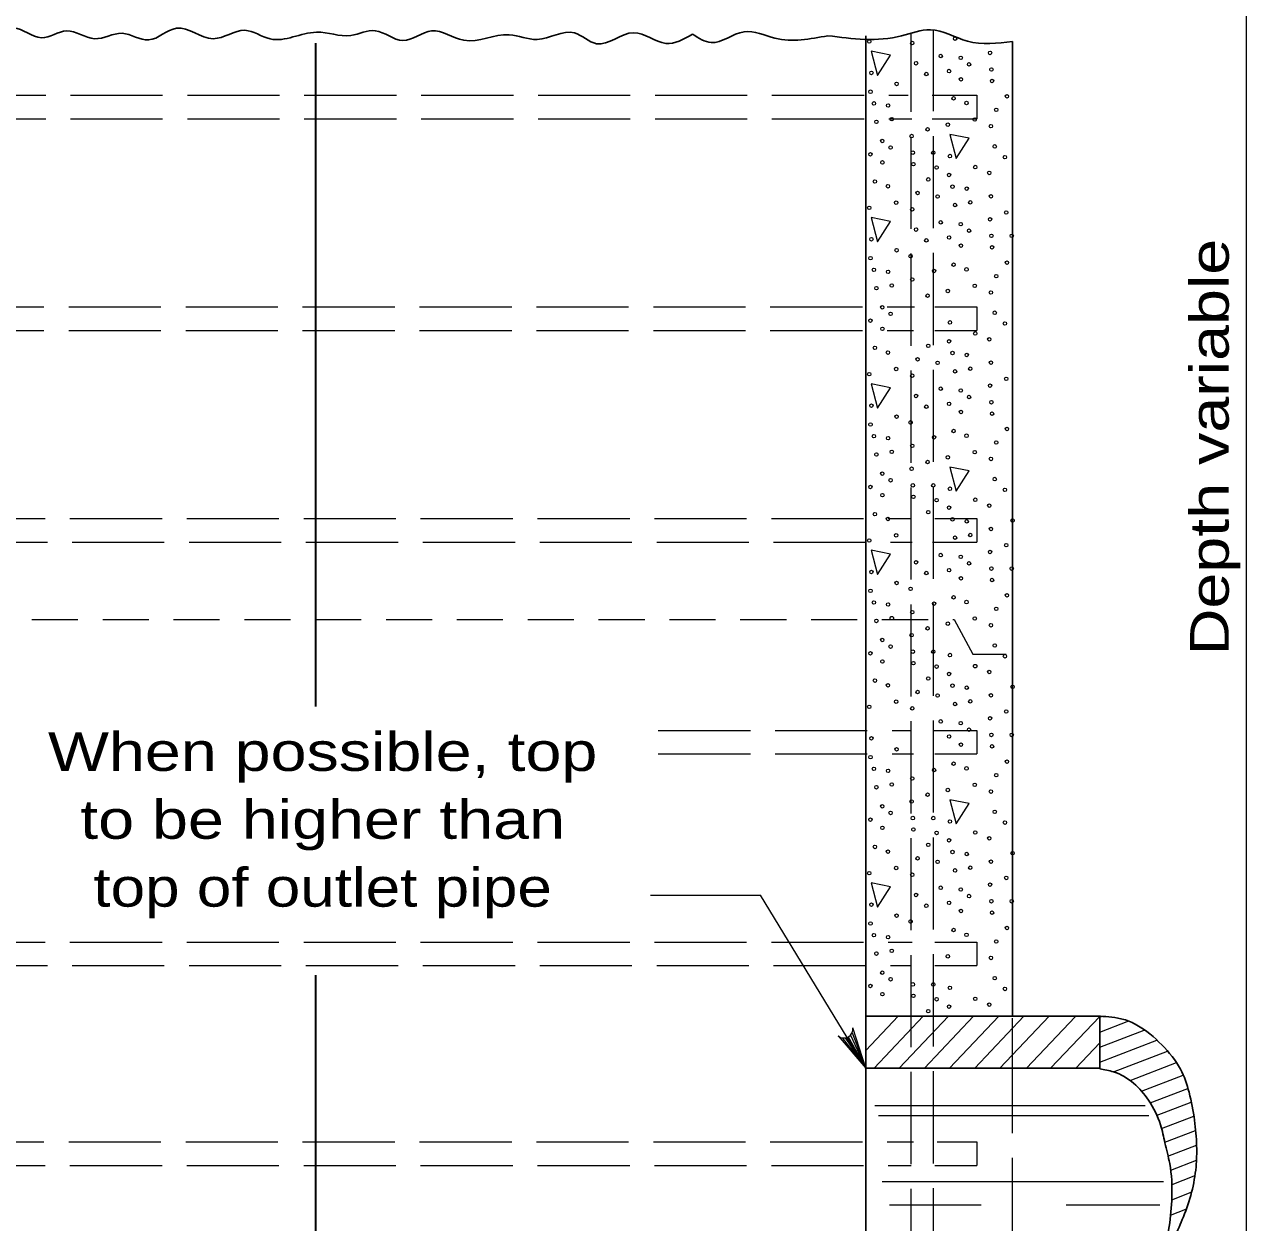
# Model space of a CAD drawing. Extents: x 1329.9 to 1363.9, y 715.5 to 737.5.
# Drawn here: x 1334.495 to 1339.429, y 723.847 to 728.685 of the extents above; entities that cross this region are included whole.
import ezdxf
from ezdxf.enums import TextEntityAlignment as Align

# ---------------------------------------------------------------- set-up
doc = ezdxf.new("R2010")
doc.units = 0
doc.header["$LTSCALE"] = 0.062
doc.linetypes.add('LONG_DASHED', pattern=[7.5, 6, -1.5])
doc.linetypes.add('MEDIUM_DASHED', pattern=[4.5, 3, -1.5])
doc.layers.add('1', color=7, linetype='Continuous', lineweight=13)

msp = doc.modelspace()

# ---------------------------------------------------------------- linework, layer by layer
at = {"layer": '1', "linetype": 'LONG_DASHED'}
for p, q in [((1338.16467, 722.19817), (1338.16467, 728.66258)), ((1338.07492, 722.19533), (1338.07492, 728.64683)), ((1333.26492, 728.39908), (1338.06333, 728.39908)), ((1338.159, 728.39908), (1338.34008, 728.39908)), ((1338.34008, 728.39908), (1338.34008, 728.30408)), ((1333.26492, 728.30408), (1338.07692, 728.30408)), ((1338.159, 728.30408), (1338.34008, 728.30408)), ((1333.258, 727.54417), (1338.08825, 727.54417)), ((1338.17025, 727.54417), (1338.34008, 727.54417)), ((1338.34008, 727.54417), (1338.34008, 727.44925)), ((1333.258, 727.44925), (1338.08367, 727.44925)), ((1338.17025, 727.44925), (1338.34008, 727.44925)), ((1333.26258, 726.68933), (1338.07467, 726.68933)), ((1338.17025, 726.68933), (1338.34008, 726.68933)), ((1338.34008, 726.68933), (1338.34008, 726.59433)), ((1333.27167, 726.59433), (1338.07917, 726.59433)), ((1338.16125, 726.59433), (1338.34008, 726.59433)), ((1337.0535, 725.8345), (1338.07467, 725.8345)), ((1338.16575, 725.8345), (1338.34008, 725.8345)), ((1338.34008, 725.8345), (1338.34008, 725.7395)), ((1337.0535, 725.7395), (1338.08367, 725.7395)), ((1338.17025, 725.7395), (1338.34008, 725.7395)), ((1333.26258, 724.97958), (1338.07917, 724.97958)), ((1338.17025, 724.97958), (1338.34008, 724.97958)), ((1338.34008, 724.97958), (1338.34008, 724.88458)), ((1333.27167, 724.88458), (1338.07467, 724.88458)), ((1338.17025, 724.88458), (1338.34008, 724.88458)), ((1338.4845, 722.32), (1338.4845, 724.47975)), ((1333.258, 724.1725), (1338.08367, 724.1725)), ((1338.17942, 724.1725), (1338.34008, 724.1725)), ((1338.34008, 724.1725), (1338.34008, 724.0775)), ((1333.26258, 724.0775), (1338.07467, 724.0775)), ((1338.17025, 724.0775), (1338.34008, 724.0775))]:
    msp.add_line(p, q, dxfattribs=at)
at = {"layer": '1', "lineweight": 35}
for p, q in [((1335.66942, 728.60967), (1335.66942, 725.93017)), ((1335.66942, 724.84575), (1335.66942, 722.24233))]:
    msp.add_line(p, q, dxfattribs=at)
at = {"layer": '1', "lineweight": 25}
for p, q in [((1337.892, 724.68033), (1337.892, 728.63892)), ((1337.892, 724.68033), (1337.892, 720.98492)), ((1338.83592, 724.68033), (1338.4845, 724.68033)), ((1338.83592, 724.68308), (1338.83592, 724.47)), ((1338.83592, 724.47), (1337.892, 724.47))]:
    msp.add_line(p, q, dxfattribs=at)
at = {"layer": '1'}
for p, q in [((1337.91325, 728.5765), (1337.93892, 728.47917)), ((1337.91325, 727.90492), (1337.93892, 727.80758)), ((1339.42875, 719.1235), (1339.42875, 725.87033)), ((1337.02292, 725.16875), (1337.46608, 725.16875)), ((1337.892, 724.47), (1337.46608, 725.16875)), ((1337.892, 724.54233), (1338.02233, 724.68033)), ((1337.92517, 724.47), (1338.12375, 724.68033)), ((1338.02675, 724.47), (1338.22533, 724.68033)), ((1338.12817, 724.47), (1338.32683, 724.68033)), ((1338.22975, 724.47), (1338.42833, 724.68033)), ((1338.33117, 724.47), (1338.52983, 724.68033)), ((1338.43267, 724.47), (1338.63133, 724.68033)), ((1338.4845, 724.47975), (1338.4845, 724.6725)), ((1338.54092, 724.47), (1338.73683, 724.6775)), ((1338.63783, 724.47), (1338.83592, 724.67958)), ((1338.83592, 724.47), (1338.83592, 724.68308)), ((1338.83592, 724.6765), (1338.84333, 724.67933)), ((1338.83592, 724.61583), (1338.95367, 724.66125)), ((1337.83642, 724.61342), (1337.892, 724.47)), ((1338.83592, 724.55517), (1339.01525, 724.62425)), ((1337.79633, 724.59308), (1337.892, 724.47)), ((1337.80783, 724.59283), (1337.892, 724.47)), ((1337.82108, 724.59708), (1337.892, 724.47)), ((1337.82967, 724.60375), (1337.892, 724.47)), ((1338.73942, 724.47), (1338.83592, 724.57217)), ((1338.83592, 724.49458), (1339.066, 724.58317)), ((1338.89217, 724.45558), (1339.10967, 724.53942)), ((1338.95833, 724.42042), (1339.14642, 724.49292)), ((1339.00492, 724.37775), (1339.17258, 724.44242)), ((1339.03925, 724.33033), (1339.19108, 724.38883)), ((1337.92833, 724.31933), (1339.01942, 724.31933)), ((1339.06742, 724.2805), (1339.20533, 724.33367)), ((1337.94325, 724.28), (1339.03425, 724.28)), ((1339.08525, 724.22667), (1339.21575, 724.277)), ((1339.09833, 724.17108), (1339.22283, 724.21908)), ((1339.11133, 724.1155), (1339.22692, 724.16008)), ((1339.123, 724.05933), (1339.22667, 724.09925)), ((1339.12783, 724.00058), (1339.21792, 724.03525)), ((1337.958, 724.01283), (1339.09392, 724.01283)), ((1339.12658, 723.93942), (1339.20558, 723.96983)), ((1337.98775, 723.9185), (1338.35783, 723.9185)), ((1338.70092, 723.9185), (1339.07875, 723.9185)), ((1339.122, 723.877), (1339.18375, 723.90083))]:
    msp.add_line(p, q, dxfattribs=at)
for points in [[(1339.42875, 725.87033), (1339.42875, 729.46942), (1339.42875, 732.83242)], [(1337.93892, 728.47917), (1337.99108, 728.56133), (1337.91325, 728.5765)], [(1337.93892, 727.80758), (1337.99108, 727.88975), (1337.91325, 727.90492)], [(1337.78067, 724.6005), (1337.892, 724.47), (1337.83942, 724.63333)]]:
    msp.add_lwpolyline(points, dxfattribs=at)
at = {"layer": '1', "lineweight": 25}
msp.add_lwpolyline([(1338.4845, 728.61575), (1338.4845, 724.68033), (1337.892, 724.68033)], dxfattribs=at)
at = {"layer": '1'}
for points in [[(1338.23042, 728.24067), (1338.256, 728.14342), (1338.30833, 728.22558)], [(1337.91325, 727.23317), (1337.93892, 727.13592), (1337.99108, 727.21808)], [(1338.23042, 726.89742), (1338.256, 726.80008), (1338.30833, 726.88225)], [(1337.91325, 726.56158), (1337.93892, 726.46425), (1337.99108, 726.54642)], [(1338.23042, 725.55408), (1338.256, 725.45675), (1338.30833, 725.53892)], [(1337.91325, 725.21825), (1337.93892, 725.121), (1337.99108, 725.20317)]]:
    msp.add_lwpolyline(points, close=True, dxfattribs=at)
at = {"layer": '1', "linetype": 'MEDIUM_DASHED'}
msp.add_lwpolyline([(1333.095, 726.28267), (1338.24792, 726.28267), (1338.32433, 726.14242), (1338.45892, 726.14242)], dxfattribs=at)
at = {"layer": '1'}
msp.add_arc((1337.80343, 724.62878), 0.03631, 231.25375, 7.07988, dxfattribs=at)
for centre in [(1337.90555, 728.61603), (1338.07943, 728.60971), (1338.25182, 728.62722), (1338.1942, 728.55715), (1338.27503, 728.55015), (1338.39351, 728.5698), (1338.09486, 728.5281), (1338.30871, 728.52357), (1338.39863, 728.50269), (1337.91411, 728.48909), (1338.13599, 728.48456), (1338.22761, 728.49637), (1338.27588, 728.4634), (1338.40117, 728.45646), (1337.91068, 728.41291), (1338.01604, 728.44465), (1337.92442, 728.36579), (1337.98178, 728.35756), (1338.2459, 728.38633), (1338.29814, 728.3673), (1338.46112, 728.39478), (1338.41804, 728.3401), (1337.93462, 728.2914), (1337.99632, 728.30232), (1338.14133, 728.26118), (1338.22275, 728.28021), (1338.33149, 728.30108), (1338.39663, 728.27388), (1337.95783, 728.21433), (1338.07631, 728.23398), (1337.91041, 728.16054), (1337.99151, 728.18774), (1338.08143, 728.16687), (1338.1637, 728.16687), (1338.41206, 728.19228), (1337.95868, 728.12758), (1338.08397, 728.12064), (1338.17739, 728.10704), (1338.23131, 728.15327), (1338.33324, 728.10883), (1338.45319, 728.14873), (1338.14392, 728.05896), (1338.22788, 728.07709), (1338.38975, 728.08526), (1337.9287, 728.05051), (1337.98094, 728.03148), (1338.24162, 728.02996), (1338.29898, 728.02174), (1338.01429, 727.96526), (1338.10084, 728.00427), (1338.18162, 727.99006), (1338.31352, 727.96649), (1338.39663, 727.9909), (1337.90555, 727.94439), (1338.07943, 727.93806), (1338.25182, 727.95558), (1338.45853, 727.92536), (1338.1942, 727.8855), (1338.27503, 727.87851), (1338.39351, 727.89815), (1337.91411, 727.81744), (1338.09486, 727.85646), (1338.13599, 727.81291), (1338.22761, 727.82472), (1338.30871, 727.85192), (1338.39863, 727.83104), (1338.48089, 727.83104), (1338.01604, 727.773), (1338.27588, 727.79175), (1338.40117, 727.78481), (1337.91068, 727.74127), (1338.07255, 727.74944), (1338.2459, 727.71468), (1338.46112, 727.72313), (1337.92442, 727.69414), (1337.98178, 727.68591), (1338.16708, 727.68933), (1338.29814, 727.69565), (1338.41804, 727.66845), (1337.93462, 727.61976), (1337.99632, 727.63067), (1338.07943, 727.65507), (1338.33149, 727.62944), (1338.14133, 727.58953), (1338.22275, 727.60856), (1338.39663, 727.60224), (1337.95783, 727.54269), (1337.99151, 727.5161), (1338.41206, 727.52063), (1337.91041, 727.4889), (1338.23131, 727.48162), (1338.45319, 727.47709), (1337.95868, 727.45593), (1338.33324, 727.43718), (1337.9287, 727.37886), (1338.14392, 727.38731), (1338.22788, 727.40545), (1338.38975, 727.41362), (1337.98094, 727.35983), (1338.10084, 727.33263), (1338.18162, 727.31841), (1338.24162, 727.35832), (1338.29898, 727.35009), (1338.39663, 727.31925), (1337.90555, 727.27274), (1338.01429, 727.29362), (1338.07943, 727.26641), (1338.25182, 727.28393), (1338.31352, 727.29485), (1338.39351, 727.22651), (1338.45853, 727.25371), (1338.09486, 727.18481), (1338.1942, 727.21386), (1338.27503, 727.20686), (1338.30871, 727.18028), (1337.91411, 727.1458), (1338.13599, 727.14126), (1338.22761, 727.15307), (1338.27588, 727.12011), (1338.39863, 727.1594), (1337.91068, 727.06962), (1338.01604, 727.10136), (1338.07255, 727.07779), (1338.40117, 727.11317), (1337.92442, 727.0225), (1338.2459, 727.04304), (1338.29814, 727.02401), (1338.46112, 727.05149), (1337.98178, 727.01427), (1338.07943, 726.98343), (1338.16708, 727.01768), (1338.41804, 726.99681), (1337.93462, 726.94811), (1337.99632, 726.95903), (1338.22275, 726.93692), (1338.33149, 726.95779), (1338.39663, 726.93059), (1338.07631, 726.89069), (1338.14133, 726.91789), (1337.95783, 726.87104), (1337.99151, 726.84445), (1338.08143, 726.82358), (1338.1637, 726.82358), (1338.41206, 726.84899), (1337.91041, 726.81725), (1337.95868, 726.78429), (1338.08397, 726.77734), (1338.23131, 726.80998), (1338.45319, 726.80544), (1338.17739, 726.76374), (1338.22788, 726.7338), (1338.33324, 726.76554), (1338.38975, 726.74197), (1337.9287, 726.70721), (1337.98094, 726.68818), (1338.14392, 726.71567), (1338.24162, 726.68667), (1338.29898, 726.67845), (1338.48428, 726.68186), (1338.39663, 726.64761), (1337.90555, 726.60109), (1338.01429, 726.62197), (1338.25182, 726.61229), (1338.31352, 726.6232), (1338.45853, 726.58206), (1338.1942, 726.54221), (1338.27503, 726.53522), (1338.39351, 726.55486), (1338.09486, 726.51316), (1338.22761, 726.48143), (1338.30871, 726.50863), (1338.39863, 726.48775), (1338.48089, 726.48775), (1337.91411, 726.47415), (1338.01604, 726.42971), (1338.13599, 726.46962), (1338.27588, 726.44846), (1338.40117, 726.44152), (1337.91068, 726.39798), (1338.07255, 726.40615), (1338.46112, 726.37984), (1337.92442, 726.35085), (1337.98178, 726.34262), (1338.16708, 726.34604), (1338.2459, 726.37139), (1338.29814, 726.35236), (1338.07943, 726.31178), (1338.33149, 726.28615), (1338.41804, 726.32516), (1337.93462, 726.27647), (1338.14133, 726.24624), (1338.22275, 726.26527), (1338.39663, 726.25895), (1337.95783, 726.19939), (1338.07631, 726.21904), (1337.91041, 726.14561), (1337.99151, 726.17281), (1338.08143, 726.15193), (1338.1637, 726.15193), (1338.23131, 726.13833), (1338.41206, 726.17734), (1338.45319, 726.1338), (1337.95868, 726.11264), (1338.08397, 726.1057), (1338.17739, 726.0921), (1337.9287, 726.03557), (1338.14392, 726.04402), (1338.22788, 726.06215), (1338.38975, 726.07033), (1337.98094, 726.01654), (1338.10084, 725.98934), (1338.24162, 726.01503), (1338.29898, 726.0068), (1338.48428, 726.01021), (1338.01429, 725.95033), (1338.18162, 725.97512), (1338.25182, 725.94064), (1338.31352, 725.95156), (1338.39663, 725.97596), (1337.90555, 725.92945), (1338.07943, 725.92312), (1338.45853, 725.91042), (1338.1942, 725.87057), (1338.27503, 725.86357), (1338.30871, 725.83699), (1338.39351, 725.88322), (1337.91411, 725.80251), (1338.22761, 725.80978), (1338.39863, 725.81611), (1338.48089, 725.81611), (1338.01604, 725.75807), (1338.27588, 725.77682), (1338.40117, 725.76988), (1337.91068, 725.72633), (1338.2459, 725.69975), (1338.46112, 725.7082), (1337.92442, 725.6792), (1337.98178, 725.67098), (1338.07943, 725.64014), (1338.16708, 725.67439), (1338.29814, 725.68072), (1338.41804, 725.65351), (1337.93462, 725.60482), (1337.99632, 725.61573), (1338.22275, 725.59363), (1338.33149, 725.6145), (1338.07631, 725.54739), (1338.14133, 725.5746), (1338.39663, 725.5873), (1337.95783, 725.52775), (1337.99151, 725.50116), (1338.41206, 725.5057), (1337.91041, 725.47396), (1337.95868, 725.44099), (1338.08143, 725.48029), (1338.1637, 725.48029), (1338.23131, 725.46668), (1338.45319, 725.46215), (1338.08397, 725.43405), (1338.17739, 725.42045), (1338.33324, 725.42224), (1338.38975, 725.39868), (1337.9287, 725.36392), (1337.98094, 725.34489), (1338.14392, 725.37237), (1338.22788, 725.39051), (1338.24162, 725.34338), (1338.10084, 725.31769), (1338.18162, 725.30347), (1338.29898, 725.33515), (1338.39663, 725.30431), (1338.48428, 725.33857), (1337.90555, 725.2578), (1338.01429, 725.27868), (1338.07943, 725.25148), (1338.25182, 725.269), (1338.31352, 725.27991), (1338.1942, 725.19892), (1338.39351, 725.21157), (1338.45853, 725.23877), (1338.09486, 725.16987), (1338.27503, 725.19193), (1338.30871, 725.16534), (1337.91411, 725.13086), (1338.13599, 725.12633), (1338.22761, 725.13814), (1338.27588, 725.10517), (1338.39863, 725.14446), (1338.40117, 725.09823), (1338.48089, 725.14446), (1337.91068, 725.05469), (1338.01604, 725.08642), (1338.07255, 725.06286), (1337.92442, 725.00756), (1337.98178, 724.99933), (1338.2459, 725.0281), (1338.29814, 725.00907), (1338.46112, 725.03655), (1338.41804, 724.98187), (1337.93462, 724.93317), (1337.99632, 724.94409), (1338.22275, 724.92198), (1338.39663, 724.91566), (1337.95783, 724.8561), (1337.91041, 724.80232), (1337.99151, 724.82952), (1338.08143, 724.80864), (1338.1637, 724.80864), (1338.41206, 724.83405), (1337.95868, 724.76935), (1338.08397, 724.76241), (1338.23131, 724.79504), (1338.33324, 724.7506), (1338.45319, 724.79051), (1338.17739, 724.74881), (1338.22788, 724.71886), (1338.38975, 724.72703), (1338.14392, 724.70073)]:
    msp.add_ellipse(centre, major_axis=(0, 0.00718), ratio=0.944544, dxfattribs=at)
at = {"layer": '1', "linetype": 'LONG_DASHED'}
msp.add_ellipse((1337.99632, 726.28738), major_axis=(0, 0.00718), ratio=0.944544, dxfattribs=at)
at = {"layer": '1', "linetype": 'MEDIUM_DASHED'}
msp.add_ellipse((1338.33324, 726.09389), major_axis=(0, 0.00718), ratio=0.944544, dxfattribs=at)
at = {"layer": '1', "lineweight": 25}
for points in [[(1333.52008, 728.67558), (1333.764, 728.62533), (1333.95642, 728.66133), (1334.06917, 728.616), (1334.22383, 728.66058), (1334.33658, 728.62017), (1334.45125, 728.66942), (1334.564, 728.63092), (1334.66558, 728.65867), (1334.77825, 728.627), (1334.88925, 728.64892), (1334.99642, 728.62208), (1335.10917, 728.66942), (1335.25733, 728.62725), (1335.385, 728.661), (1335.4865, 728.62633), (1335.67392, 728.6535), (1335.81275, 728.6405), (1335.91158, 728.65942), (1336.02233, 728.62), (1336.13892, 728.6585), (1336.26842, 728.62108), (1336.45208, 728.64333), (1336.56475, 728.62433), (1336.71575, 728.65042), (1336.80425, 728.60692), (1336.95433, 728.6515), (1337.08383, 728.60817), (1337.19208, 728.64558)], [(1337.19208, 728.64558), (1337.26683, 728.61158), (1337.40008, 728.65517), (1337.52492, 728.62933), (1337.73817, 728.63925)], [(1337.73817, 728.63925), (1338.03608, 728.63842), (1338.15258, 728.66333), (1338.30167, 728.61725), (1338.4845, 728.61575)], [(1339.09042, 723.651), (1339.13833, 723.787), (1339.17375, 723.86975), (1339.22483, 724.07217), (1339.22725, 724.15625), (1339.21867, 724.26008), (1339.1965, 724.373), (1339.16217, 724.46625), (1339.08633, 724.56467), (1338.98608, 724.64475), (1338.93308, 724.66717), (1338.83592, 724.68033)], [(1338.83592, 724.46725), (1338.89217, 724.4555), (1338.97292, 724.4095), (1339.03275, 724.34133), (1339.08175, 724.24158), (1339.09883, 724.16925), (1339.1185, 724.08517), (1339.12725, 723.94992), (1339.11625, 723.83167), (1339.09558, 723.71467), (1339.08633, 723.647)]]:
    msp.add_spline(points, degree=3, dxfattribs=at)

# ---------------------------------------------------------------- texts
at = {"layer": '1', "width": 1.25}
msp.add_text('Depth variable', height=0.156, rotation=90, dxfattribs=at).set_placement((1339.35683, 726.13783))
at = {"layer": '1'}
for s, width, p in [('When possible, top', 1.25, (1335.69892, 725.67075)), ('to be higher than', 1.25, (1335.69888, 725.39667)), ('top of outlet pipe', 1.2, (1335.69892, 725.12258))]:
    msp.add_text(s, height=0.156, dxfattribs=dict(at, width=width)).set_placement(p, align=Align.CENTER)

doc.saveas('drawing.dxf')
